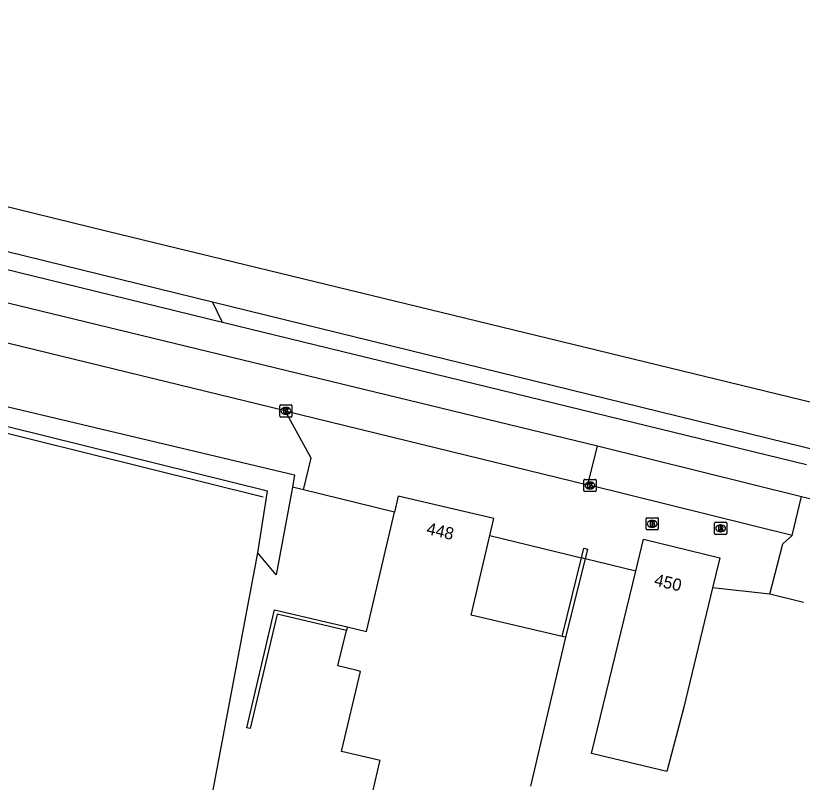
# Model space of a CAD drawing. Extents: x 163863 to 164644, y 379566 to 382155.
# Drawn here: x 164415.3 to 164479.7, y 382091.7 to 382154.5 of the extents above; entities that cross this region are included whole.
import ezdxf

# ---------------------------------------------------------------- set-up
doc = ezdxf.new("R2010")
doc.units = 0
for name, color, linetype in [('IMGEO_Brandkraan', 7, 'Continuous'), ('IMGEO_Fietspad_gesloten', 7, 'Continuous'), ('IMGEO_Grasland_agrarisch', 7, 'Continuous'), ('IMGEO_Groenvoorziening', 7, 'Continuous'), ('IMGEO_Hek', 7, 'Continuous'), ('IMGEO_Kolk', 7, 'Continuous'), ('IMGEO_Muur', 7, 'Continuous'), ('IMGEO_Pand', 7, 'Continuous'), ('IMGEO_Pand_nummerreeks', 7, 'Continuous'), ('IMGEO_Rijbaan_regionaal_gesloten', 7, 'Continuous'), ('IMGEO_Rioolput', 7, 'Continuous'), ('IMGEO_Voetpad_open', 7, 'Continuous'), ('IMGEO_Waterloop', 7, 'Continuous')]:
    doc.layers.add(name, color=color, linetype=linetype)

msp = doc.modelspace()

# ---------------------------------------------------------------- linework, layer by layer
at = {"layer": 'IMGEO_Brandkraan'}
for p, q in [((164466.923, 382112.481), (164466.923, 382113.333)), ((164466.998, 382113.407), (164467.85, 382113.407)), ((164467.924, 382113.333), (164467.924, 382112.481)), ((164467.434, 382112.627), (164467.409, 382112.627)), ((164467.411, 382113.187), (164467.436, 382113.187)), ((164467.85, 382112.407), (164466.998, 382112.407))]:
    msp.add_line(p, q, dxfattribs=at)
for points in [[(164466.923, 382112.481), (164466.923, 382113.333)], [(164466.998, 382113.407), (164467.85, 382113.407)], [(164467.924, 382113.333), (164467.924, 382112.481)], [(164467.271, 382113.107), (164467.271, 382112.707), (164467.484, 382112.707)], [(164467.502, 382113.107), (164467.271, 382113.107)], [(164467.45, 382113.026), (164467.396, 382113.026), (164467.396, 382112.95)], [(164467.396, 382112.95), (164467.449, 382112.95)], [(164467.458, 382112.874), (164467.396, 382112.874), (164467.396, 382112.793)], [(164467.396, 382112.793), (164467.458, 382112.793)], [(164467.85, 382112.407), (164466.998, 382112.407)]]:
    msp.add_lwpolyline(points, dxfattribs=at)
for centre, radius, start, end in [((164467, 382113.331), 0.0765, 91.55205, 178.44795), ((164467, 382113.331), 0.0765, 91.55205, 178.44795), ((164467.848, 382113.331), 0.0765, 1.55205, 88.44795), ((164467.848, 382113.331), 0.0765, 1.55205, 88.44795), ((164467.451, 382112.988), 0.0379, 267.82845, 90.93552), ((164467.459, 382112.833), 0.0404, 269.87594, 90.50774), ((164467.49, 382112.958), 0.251, 268.66757, 293.53466), ((164467.506, 382112.962), 0.145, 59.4692, 91.53667), ((164467.531, 382113.009), 0.0922, 285.51372, 58.15012), ((164467.536, 382112.817), 0.105, 301.31148, 78.98903), ((164467, 382112.483), 0.0765, 181.55205, 268.44795), ((164467, 382112.483), 0.0765, 181.55205, 268.44795), ((164467.848, 382112.483), 0.0765, 271.55205, 358.44795), ((164467.848, 382112.483), 0.0765, 271.55205, 358.44795)]:
    msp.add_arc(centre, radius, start, end, dxfattribs=at)
for centre, major_axis, ratio, start_param, end_param in [((164467.41, 382112.907), (-0.387, 0.002), 0.722429, 4.712389, 7.853982), ((164467.435, 382112.907), (-0.39, 0.002), 0.717154, 1.570796, 4.712389)]:
    msp.add_ellipse(centre, major_axis=major_axis, ratio=ratio, start_param=start_param, end_param=end_param, dxfattribs=at)
at = {"layer": 'IMGEO_Fietspad_gesloten'}
for points in [[(164362.677, 382143.726), (164380.086, 382139.395), (164383.897, 382138.464), (164391.868, 382136.525), (164462.951, 382119.296)], [(164432.227, 382129.4), (164397.276, 382137.925)], [(164480.06, 382117.733), (164432.227, 382129.4)], [(164462.951, 382119.296), (164479.662, 382115.151)], [(164479.662, 382115.151), (164500, 382110.112), (164547.275, 382098.592)]]:
    msp.add_lwpolyline(points, dxfattribs=at)
at = {"layer": 'IMGEO_Grasland_agrarisch'}
msp.add_lwpolyline([(164489.947, 382084.16), (164470.866, 382080.468), (164474.509, 382073.296), (164481.916, 382059.76), (164475.746, 382056.934), (164473.679, 382054.908), (164457.891, 382046.244), (164453.634, 382045.535), (164441.623, 382046.775), (164434.006, 382047.227), (164433.098, 382049.676), (164428.708, 382060.087), (164426.215, 382066.784), (164427.684, 382071.122), (164435.113, 382110.541)], dxfattribs=at)
at = {"layer": 'IMGEO_Groenvoorziening'}
for points in [[(164438.862, 382115.685), (164437.949, 382115.908)], [(164479.816, 382106.45), (164477.07, 382107.139)]]:
    msp.add_lwpolyline(points, dxfattribs=at)
at = {"layer": 'IMGEO_Hek'}
msp.add_lwpolyline([(164392.898, 382125.718), (164435.546, 382115.127)], dxfattribs=at)
at = {"layer": 'IMGEO_Kolk'}
for p, q in [((164436.919, 382121.724), (164436.919, 382122.576)), ((164436.994, 382122.65), (164437.846, 382122.65)), ((164437.407, 382122.43), (164437.432, 382122.43)), ((164437.92, 382122.576), (164437.92, 382121.724)), ((164437.846, 382121.65), (164436.994, 382121.65)), ((164437.43, 382121.87), (164437.405, 382121.87)), ((164461.833, 382115.618), (164461.833, 382116.47)), ((164461.908, 382116.544), (164462.76, 382116.544)), ((164462.834, 382116.47), (164462.834, 382115.618)), ((164462.321, 382116.324), (164462.346, 382116.324)), ((164462.76, 382115.544), (164461.908, 382115.544)), ((164462.344, 382115.764), (164462.319, 382115.764))]:
    msp.add_line(p, q, dxfattribs=at)
for points in [[(164436.919, 382121.724), (164436.919, 382122.576)], [(164436.994, 382122.65), (164437.846, 382122.65)], [(164437.24, 382122.35), (164437.363, 382122.35), (164437.363, 382122.199), (164437.493, 382122.35), (164437.657, 382122.35), (164437.511, 382122.199), (164437.664, 382121.95), (164437.512, 382121.95), (164437.427, 382122.114), (164437.363, 382122.047), (164437.363, 382121.95), (164437.24, 382121.95), (164437.24, 382122.35)], [(164437.92, 382122.576), (164437.92, 382121.724)], [(164437.846, 382121.65), (164436.994, 382121.65)], [(164461.833, 382115.618), (164461.833, 382116.47)], [(164461.908, 382116.544), (164462.76, 382116.544)], [(164462.834, 382116.47), (164462.834, 382115.618)], [(164462.154, 382116.244), (164462.277, 382116.244), (164462.277, 382116.093), (164462.407, 382116.244), (164462.571, 382116.244), (164462.425, 382116.093), (164462.578, 382115.844), (164462.426, 382115.844), (164462.341, 382116.008), (164462.277, 382115.941), (164462.277, 382115.844), (164462.154, 382115.844), (164462.154, 382116.244)], [(164462.76, 382115.544), (164461.908, 382115.544)]]:
    msp.add_lwpolyline(points, dxfattribs=at)
for centre, start, end in [((164436.996, 382122.574), 91.55205, 178.44795), ((164436.996, 382122.574), 91.55205, 178.44795), ((164437.844, 382122.574), 1.55205, 88.44795), ((164437.844, 382122.574), 1.55205, 88.44795), ((164436.996, 382121.726), 181.55205, 268.44795), ((164436.996, 382121.726), 181.55205, 268.44795), ((164437.844, 382121.726), 271.55205, 358.44795), ((164437.844, 382121.726), 271.55205, 358.44795), ((164461.91, 382116.468), 91.55205, 178.44795), ((164461.91, 382116.468), 91.55205, 178.44795), ((164462.758, 382116.468), 1.55205, 88.44795), ((164462.758, 382116.468), 1.55205, 88.44795), ((164461.91, 382115.62), 181.55205, 268.44795), ((164461.91, 382115.62), 181.55205, 268.44795), ((164462.758, 382115.62), 271.55205, 358.44795), ((164462.758, 382115.62), 271.55205, 358.44795)]:
    msp.add_arc(centre, 0.0765, start, end, dxfattribs=at)
for centre, major_axis, ratio, start_param, end_param in [((164437.406, 382122.15), (-0.387, 0.002), 0.722429, 4.712389, 7.853982), ((164437.431, 382122.15), (-0.39, 0.002), 0.717154, 1.570796, 4.712389), ((164462.32, 382116.044), (-0.387, 0.002), 0.722429, 4.712389, 7.853982), ((164462.345, 382116.044), (-0.39, 0.002), 0.717154, 1.570796, 4.712389)]:
    msp.add_ellipse(centre, major_axis=major_axis, ratio=ratio, start_param=start_param, end_param=end_param, dxfattribs=at)
at = {"layer": 'IMGEO_Muur'}
for points in [[(164461.626, 382110.122), (164461.82, 382110.923), (164462.12, 382110.839), (164461.923, 382110.049)], [(164460.058, 382103.676), (164461.626, 382110.122)], [(164461.923, 382110.049), (164460.316, 382103.616)], [(164461.923, 382110.049), (164461.626, 382110.122)], [(164442.382, 382104.166), (164436.699, 382105.494), (164434.502, 382096.136), (164434.21, 382096.204), (164436.475, 382105.855), (164442.453, 382104.458)]]:
    msp.add_lwpolyline(points, dxfattribs=at)
at = {"layer": 'IMGEO_Pand'}
for points in [[(164454.119, 382111.961), (164454.442, 382113.336), (164446.627, 382115.173), (164446.32, 382113.869)], [(164442.453, 382104.458), (164444.018, 382104.074), (164446.32, 382113.869)], [(164460.058, 382103.676), (164452.585, 382105.433), (164454.119, 382111.961)], [(164466.081, 382109.031), (164466.714, 382111.636), (164472.96, 382110.125), (164472.37, 382107.672)], [(164472.37, 382107.672), (164470.021, 382097.898), (164468.635, 382092.61), (164462.447, 382094.094), (164466.081, 382109.031)], [(164442.453, 382104.458), (164442.382, 382104.166)], [(164455.961, 382086.579), (164449.039, 382088.206), (164444.154, 382089.354), (164445.114, 382093.437), (164445.132, 382093.514), (164441.983, 382094.254), (164443.527, 382100.824), (164443.269, 382100.888), (164441.676, 382101.286), (164442.382, 382104.166)], [(164460.316, 382103.616), (164457.45, 382091.42)], [(164460.316, 382103.616), (164460.058, 382103.676)]]:
    msp.add_lwpolyline(points, dxfattribs=at)
at = {"layer": 'IMGEO_Rijbaan_regionaal_gesloten'}
for points in [[(164350.865, 382154.51), (164352.346, 382154.141), (164422.808, 382136.877), (164448.236, 382130.698), (164525.74, 382111.863), (164595.632, 382094.807)], [(164399.244, 382138.965), (164431.396, 382131.087)], [(164431.396, 382131.087), (164481.274, 382118.867)]]:
    msp.add_lwpolyline(points, dxfattribs=at)
at = {"layer": 'IMGEO_Rioolput'}
for p, q in [((164472.53, 382112.11), (164472.53, 382112.962)), ((164472.605, 382113.036), (164473.457, 382113.036)), ((164473.018, 382112.816), (164473.043, 382112.816)), ((164473.531, 382112.962), (164473.531, 382112.11)), ((164473.457, 382112.036), (164472.605, 382112.036)), ((164473.041, 382112.256), (164473.016, 382112.256))]:
    msp.add_line(p, q, dxfattribs=at)
for points in [[(164472.53, 382112.11), (164472.53, 382112.962)], [(164472.605, 382113.036), (164473.457, 382113.036)], [(164473.119, 382112.734), (164472.867, 382112.736), (164472.867, 382112.336)], [(164473.045, 382112.655), (164472.991, 382112.655), (164472.991, 382112.574)], [(164473.531, 382112.962), (164473.531, 382112.11)], [(164473.457, 382112.036), (164472.605, 382112.036)], [(164472.867, 382112.336), (164472.991, 382112.336), (164472.991, 382112.498), (164473.002, 382112.498)], [(164472.991, 382112.574), (164473.043, 382112.574)], [(164473.049, 382112.469), (164473.12, 382112.336), (164473.26, 382112.336), (164473.195, 382112.462)]]:
    msp.add_lwpolyline(points, dxfattribs=at)
for centre, radius, start, end in [((164472.607, 382112.96), 0.0765, 91.55205, 178.44795), ((164472.607, 382112.96), 0.0765, 91.55205, 178.44795), ((164473.051, 382112.559), 0.0964, 77.00612, 93.18647), ((164473.065, 382112.616), 0.0378, 276.66336, 79.67722), ((164473.118, 382112.624), 0.109, 350.36119, 89.41601), ((164473.116, 382112.624), 0.112, 277.58423, 350.98172), ((164473.455, 382112.96), 0.0765, 1.55205, 88.44795), ((164473.455, 382112.96), 0.0765, 1.55205, 88.44795), ((164472.607, 382112.112), 0.0765, 181.55205, 268.44795), ((164472.607, 382112.112), 0.0765, 181.55205, 268.44795), ((164473.001, 382112.445), 0.0533, 26.02933, 88.69889), ((164473.027, 382112.763), 0.19, 274.7715, 282.96867), ((164473.1, 382112.409), 0.108, 29.51342, 73.79051), ((164473.455, 382112.112), 0.0765, 271.55205, 358.44795), ((164473.455, 382112.112), 0.0765, 271.55205, 358.44795)]:
    msp.add_arc(centre, radius, start, end, dxfattribs=at)
for centre, major_axis, ratio, start_param, end_param in [((164473.017, 382112.536), (-0.387, 0.002), 0.722429, 4.712389, 7.853982), ((164473.042, 382112.536), (-0.39, 0.002), 0.717154, 1.570796, 4.712389)]:
    msp.add_ellipse(centre, major_axis=major_axis, ratio=ratio, start_param=start_param, end_param=end_param, dxfattribs=at)
at = {"layer": 'IMGEO_Voetpad_open'}
for points in [[(164437.356, 382122.165), (164397.339, 382131.912)], [(164432.227, 382129.4), (164431.396, 382131.087)], [(164437.356, 382122.165), (164462.152, 382116.088)], [(164438.862, 382115.685), (164439.493, 382118.283), (164437.356, 382122.165)], [(164462.152, 382116.088), (164462.951, 382119.296)], [(164478.888, 382111.958), (164462.152, 382116.088)], [(164446.32, 382113.869), (164438.862, 382115.685)], [(164478.888, 382111.958), (164479.662, 382115.151)], [(164454.119, 382111.961), (164461.626, 382110.122)], [(164477.07, 382107.139), (164478.134, 382111.273), (164478.888, 382111.958)], [(164466.081, 382109.031), (164461.923, 382110.049)], [(164477.07, 382107.139), (164472.37, 382107.672)]]:
    msp.add_lwpolyline(points, dxfattribs=at)
at = {"layer": 'IMGEO_Waterloop'}
for points in [[(164396.25, 382126.848), (164438.135, 382116.921), (164437.949, 382115.908)], [(164435.113, 382110.541), (164435.91, 382115.587), (164393.78, 382126.007), (164393.977, 382126.658)], [(164437.949, 382115.908), (164436.636, 382108.734), (164435.113, 382110.541)]]:
    msp.add_lwpolyline(points, dxfattribs=at)

# ---------------------------------------------------------------- texts
at = {"layer": 'IMGEO_Pand_nummerreeks'}
for s, rotation, p in [('448', 346.7704, (164448.874, 382112.076)), ('450', 346.77353, (164467.529, 382107.864))]:
    msp.add_text(s, height=1, rotation=rotation, dxfattribs=at).set_placement(p)

doc.saveas('drawing.dxf')
